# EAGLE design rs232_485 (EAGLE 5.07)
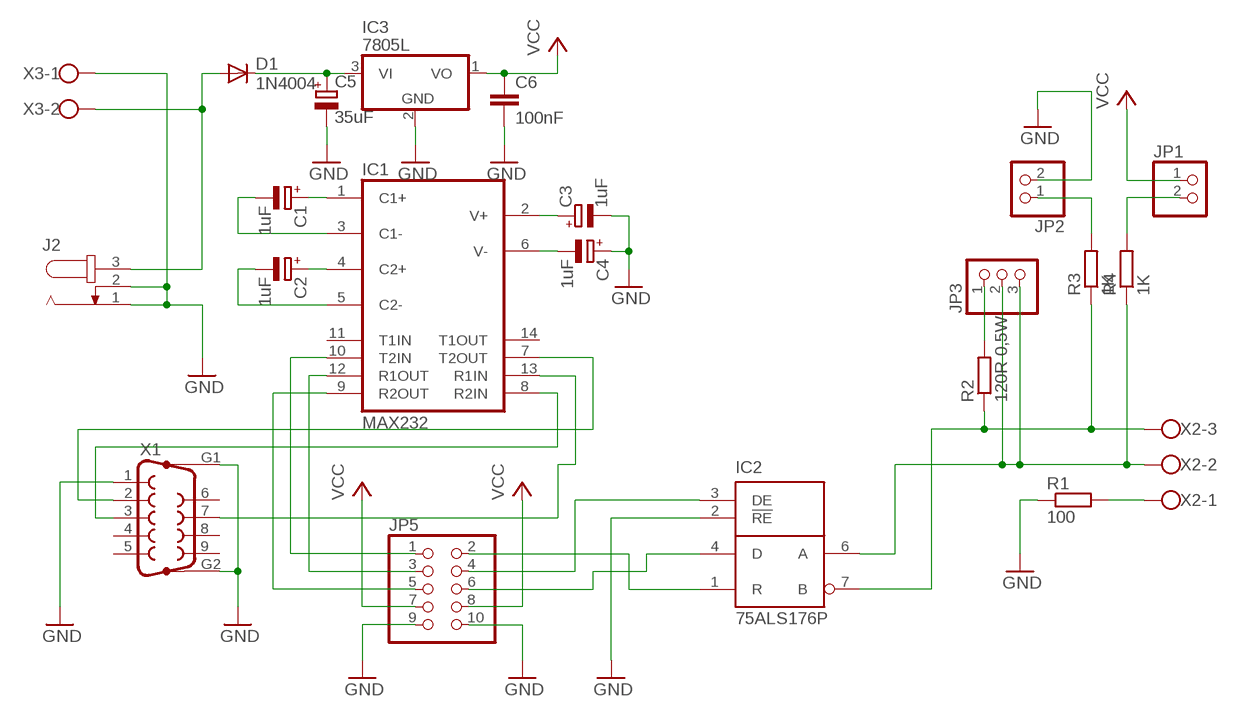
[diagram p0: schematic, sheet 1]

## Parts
C1  1uF  CPOL-EUE2,5-6E  [E2,5-6E]
C2  1uF  CPOL-EUE2,5-6E  [E2,5-6E]
C3  1uF  CPOL-EUE2,5-6E  [E2,5-6E]
C4  1uF  CPOL-EUE2,5-6E  [E2,5-6E]
C5  35uF  CPOL-EUE2.5-5  [E2,5-5]
C6  100nF  C-EU025-025X050  [C025-025X050]
D1  1N4004  [DO41-10]
IC1  MAX232  [DIL16]
IC2  75ALS176P  [DIL08]
IC3  7805L  [TO92]
J2  JACK-PLUG0  [SPC4077]
JP1  PINHD-1X2  [1X02]
JP2  PINHD-1X2  [1X02]
JP3  PINHD-1X3  [1X03]
JP5  PINHD-2X5  [2X05]
R1  100  R-EU_0204/7  [0204/7]
R2  120R 0,5W  R-EU_0204/7  [0204/7]
R3  1K  R-EU_0204/7  [0204/7]
R4  1K  R-EU_0204/7  [0204/7]
X1  F09HP  [F09HP]
X2  W237-103  [W237-103]
X3  W237-102  [W237-102]

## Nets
GND: C3.- C4.+ C5.- C6.2 IC2.2(!RE) IC3.2(GND) J2.1 J2.2 JP2.2 JP5.9 JP5.10 R1.1 X1.1 X1.G1 X1.G2 X3.1
N$1: C1.+ IC1.1(C1+)
N$2: C2.+ IC1.4(C2+)
N$3: C1.- IC1.3(C1-)
N$4: C2.- IC1.5(C2-)
N$5: C3.+ IC1.2(V+)
N$6: C4.- IC1.6(V-)
N$7: IC1.10(T2IN) JP5.1
N$8: IC2.1(R) JP5.2
N$9: IC1.8(R2IN) X1.3
N$10: IC1.7(T2OUT) X1.2
N$11: IC1.13(R1IN) X1.7
N$12: IC1.12(R1OUT) JP5.3
N$13: IC2.4(D) JP5.6
N$14: IC1.9(R2OUT) JP5.5
N$15: IC2.3(DE) JP5.4
N$16: IC2.6(A) JP3.2 JP3.3 R4.1 X2.2
N$17: IC2.7(B) R2.1 R3.1 X2.3
N$18: JP3.1 R2.2
N$19: R1.2 X2.1
N$20: JP1.2 R4.2
N$21: JP2.1 R3.2
N$22: D1.A J2.3 X3.2
N$26: C5.+ D1.C IC3.3(VI)
VCC: C6.1 IC3.1(VO) JP1.1 JP5.7 JP5.8
Unconnected: IC1.11(T1IN) IC1.14(T1OUT) X1.4 X1.5 X1.6 X1.8 X1.9

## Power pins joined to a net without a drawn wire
GND: IC1.15(GND) IC2.5(GND)
VCC: IC1.16(VCC) IC2.8(VCC)

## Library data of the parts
C1-C5 = resistor:CPOL-EU: POLARIZED CAPACITOR, European symbol
C6 = resistor:C-EU: CAPACITOR, European symbol
D1 = diode:1N4004: DIODE
IC1 = maxim:MAX232: RS232 TRANSEIVER
IC2 = texas:75ALS176: DIFFERENTIAL BUS TRANSCEIVERS TIA/EIA-422-B, TIA/EIA-422-B + TIA/EIA-422-B TIA/EIA-422-B Operate at Data Rates up to 35 Mbaud Source: http://focus.ti.com/lit/ds/symlink/sn65als176.pdf
IC3 = linear:78*: Positive VOLTAGE REGULATOR Source: http://cache.national.com/ds/LM/LM78L05.pdf http://www.fairchildsemi.com/ds/LM/LM7805.pdf
J2 = con-jack:JACK-PLUG: DC POWER JACK Power Jack, DC, Right Angle, Through Hole, Rated 5A at 16VDC, PC Terminals Distributor: Farnell (www.Farnell.de) Drawing: 84N1161.pdf / 84N1162.pdf Manufacturer: SPC Technology (www.spctechnology.com) Type: SPC4077 / SPC 4078
JP1 JP2 = pinhead:PINHD-1X2: PIN HEADER
JP3 = pinhead:PINHD-1X3: PIN HEADER
JP5 = pinhead:PINHD-2X5: PIN HEADER
R1-R4 = resistor:R-EU_: RESISTOR, European symbol
X1 = con-subd:F09HP: SUB-D
X2 = con-wago-500:W237-103: WAGO SCREW CLAMP
X3 = con-wago-500:W237-102: WAGO SCREW CLAMP

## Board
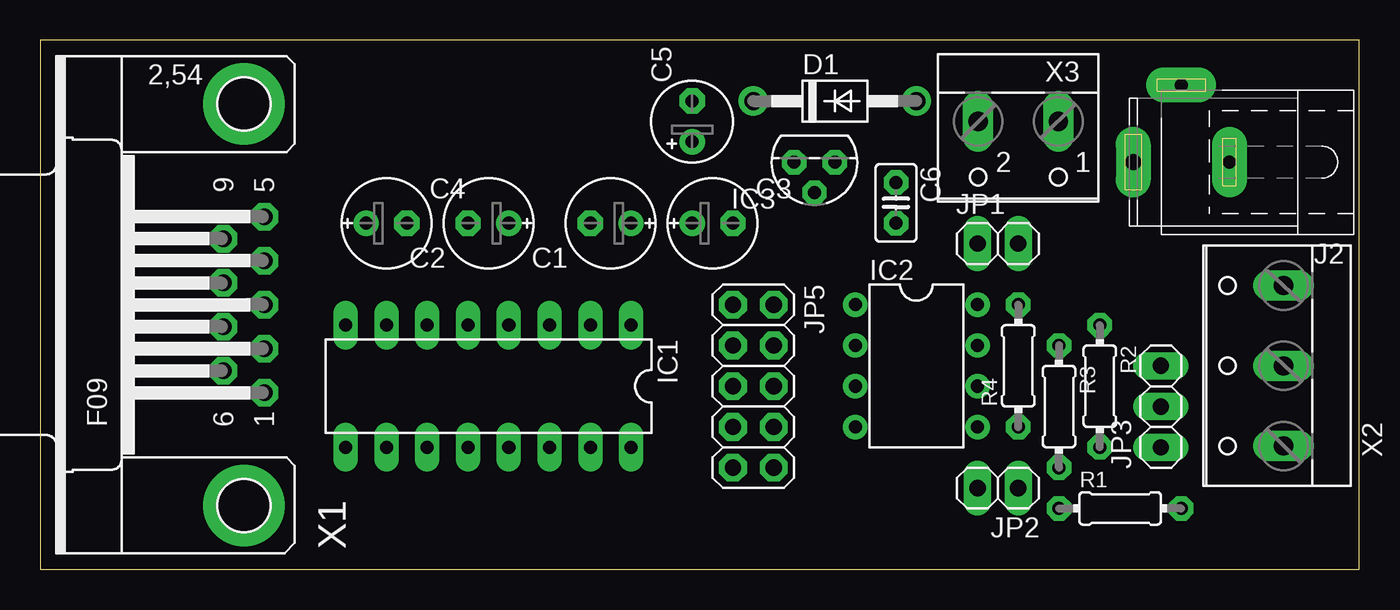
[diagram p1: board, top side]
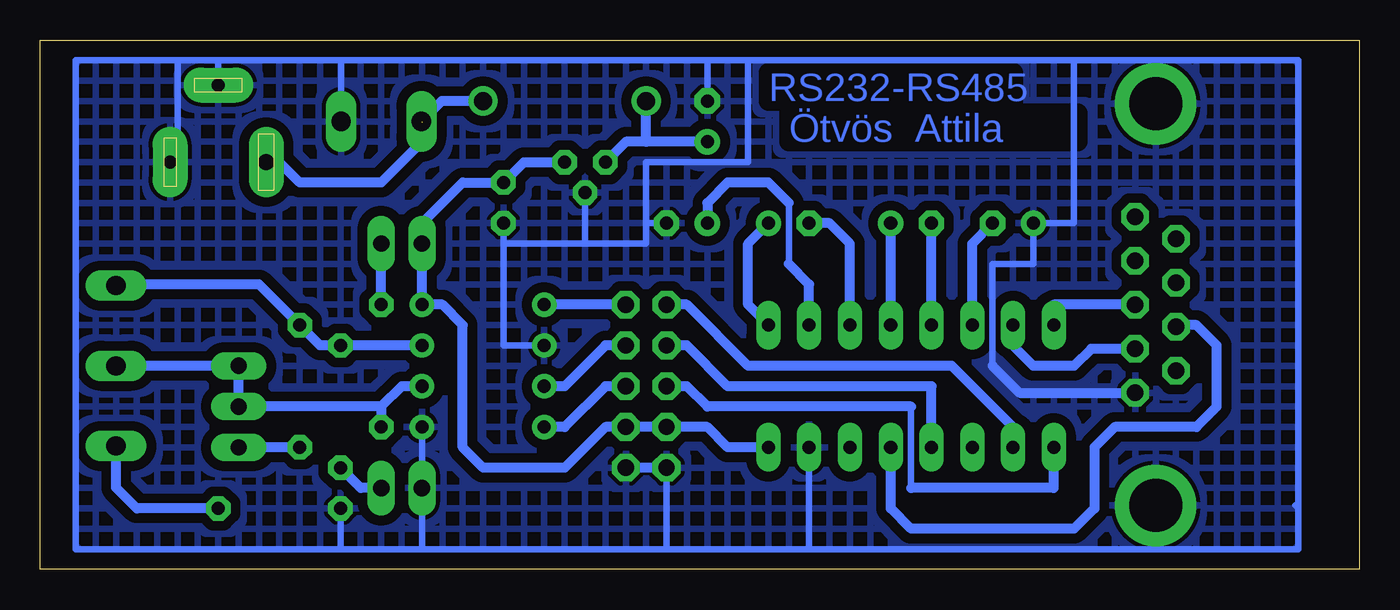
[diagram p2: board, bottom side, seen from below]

Size 82.22 x 33.01 mm. Coordinates in mm from the lower left corner, seen from the top.
Outline: 0,0 82.22,0 82.22,33.01 0,33.01 0,0
Copper layers (1*16): Top 0.035mm / dielectric 1.5mm / Bottom 0.035mm
Design rules "default *": minimum track width 10mil, minimum drill 24mil, track to track 8mil, track to pad 8mil, pad to pad 8mil, via to via 8mil, smd to smd 8mil, copper to edge 40mil, drill to drill 8mil, minimum pad ring 14mil, minimum via ring 12mil, stop-mask expansion 4mil, vias tented up to drill 0mil, thermal gap 10mil

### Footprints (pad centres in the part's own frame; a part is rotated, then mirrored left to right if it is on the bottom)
E2,5-6E = drill 0.813 pad 1.575 round: + -1.27,0 | drill 0.813 pad 1.575 octagon: - 1.27,0
E2,5-5 = drill 0.813 pad 1.6 round: + -1.27,0 | drill 0.813 pad 1.6 octagon: - 1.27,0
C025-025X050 = drill 0.813 octagon: 1 -1.27,0; 2 1.27,0
DO41-10 = drill 1.118 round: A 5.08,0; C -5.08,0
DIL16 = drill 0.813 long: 1 -8.89,-3.81; 2 -6.35,-3.81; 3 -3.81,-3.81; 4 -1.27,-3.81; 5 1.27,-3.81; 6 3.81,-3.81; 7 6.35,-3.81; 8 8.89,-3.81; 9 8.89,3.81; 10 6.35,3.81; 11 3.81,3.81; 12 1.27,3.81; 13 -1.27,3.81; 14 -3.81,3.81; 15 -6.35,3.81; 16 -8.89,3.81
DIL08 = drill 0.813 pad 1.27 round: 1 -3.81,-3.81; 2 -1.27,-3.81; 3 1.27,-3.81; 4 3.81,-3.81; 5 3.81,3.81; 6 1.27,3.81; 7 -1.27,3.81; 8 -3.81,3.81
TO92 = drill 0.813 octagon: 1 -1.27,0; 2 0,1.905; 3 1.27,0
SPC4077 = drill 0.8 pad 2.184 long: 1 -3,0; 2 0,-4.8 | drill 1 pad 2.184 long: 3 3,0
1X02 = drill 1.016 long: 1 -1.27,0; 2 1.27,0
1X03 = drill 1.016 long: 1 -2.54,0; 2 0,0; 3 2.54,0
2X05 = drill 1.016 octagon: 1 -5.08,-1.27; 2 -5.08,1.27; 3 -2.54,-1.27; 4 -2.54,1.27; 5 0,-1.27; 6 0,1.27; 7 2.54,-1.27; 8 2.54,1.27; 9 5.08,-1.27; 10 5.08,1.27
0204/7 = drill 0.813 octagon: 1 -3.81,0; 2 3.81,0
F09HP = drill 1.016 octagon: 1 -5.486,-1.27; 2 -2.743,-1.27; 3 0,-1.27; 4 2.743,-1.27; 5 5.486,-1.27; 6 -4.115,1.27; 7 -1.372,1.27; 8 1.372,1.27; 9 4.115,1.27 | drill 3.302 pad 5.08 round: G1 -12.522,0; G2 12.522,0
W237-103 = drill 1.194 long: 1 -5,-1.29; 2 0,-1.29; 3 5,-1.29
W237-102 = drill 1.194 long: 1 -2.5,-1.27; 2 2.5,-1.27

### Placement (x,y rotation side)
C1  35.56,21.59 180 top
C2  27.94,21.59 180 top
C3  41.91,21.59 0 top
C4  21.59,21.59 0 top
C5  40.64,27.94 90 top
C6  53.34,22.86 270 top
D1  49.53,29.21 0 top
IC1  27.94,11.43 180 top
IC2  54.61,12.7 270 top
IC3  48.26,25.4 180 top
J2  71.12,25.4 180 top
JP1  59.69,20.32 0 top
JP2  59.69,5.08 180 top
JP3  69.85,10.16 90 top
JP5  44.45,11.43 270 top
R1  67.31,3.81 0 top
R2  66.04,11.43 270 top
R3  63.5,10.16 270 top
R4  60.96,12.7 90 top
X1  12.7,16.51 90 top
X2  76.2,12.7 90 top
X3  60.96,26.67 180 top

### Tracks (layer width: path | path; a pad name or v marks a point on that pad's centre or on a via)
GND
  Bottom 0.406: 3.81,3.81 3.99,3.99 | 34.29,1.27 IC1.15 | 53.34,20.32 C6.2 | 44.45,21.59 44.45,20.32 48.26,20.32 | 40.64,31.75 63.5,31.75 | 63.5,31.75 71.12,31.75 | 73.66,31.75 80.01,31.75 80.01,1.27 63.5,1.27 | 73.66,31.75 71.12,31.75 | 71.12,31.75 71.08,31.71 | IC2.2 53.34,13.97 53.34,20.32 | 12.7,31.75 3.81,31.75 3.81,3.81 | 12.7,31.75 17.78,31.75 | 17.78,31.75 38.1,31.75 | 38.1,31.75 40.64,31.75 | 3.81,3.81 3.81,1.27 12.7,1.27 | 12.7,1.27 34.29,1.27 | 34.29,1.27 43.18,1.27 | 43.18,1.27 58.42,1.27 | 58.42,1.27 63.5,1.27 | 58.42,1.27 IC2.5 | 43.18,1.27 JP5.9 | 22.86,12.7 22.86,19.05 20.32,19.05 C4.+ 17.78,21.59 17.78,31.75 | 12.7,1.27 X1.G1 | 12.7,31.75 X1.G2 | 44.45,21.59 C3.- | 48.26,20.32 53.34,20.32 | 40.64,31.75 C5.- | 48.26,20.32 IC3.2 | 63.5,1.27 R1.1 | 38.1,31.75 38.1,25.4 44.45,25.4 44.45,21.59 | X3.1 63.46,31.71 63.5,31.75 | J2.1 73.66,26.67 73.66,31.75 | 71.12,31.75 J2.2
  Bottom 0.61: JP5.9 JP5.10 | X1.1 21.18,11.02 22.86,12.7
  pour Bottom (isolate 0.61, hatched): 3.81,31.75 80.01,31.75 80.01,1.27 3.81,1.27
N$1
  Bottom 0.61: C1.+ 38.1,20.32 38.1,16.51 IC1.1
N$2
  Bottom 0.61: IC1.4 C2.+
N$3
  Bottom 0.61: C1.- 33.02,21.59 31.75,20.32 IC1.3
N$4
  Bottom 0.61: IC1.5 C2.-
N$5
  Bottom 0.406: 35.56,19.05 35.56,22.86
  Bottom 0.61: IC1.2 34.29,17.78 35.56,19.05 | 35.56,22.86 36.83,24.13 39.37,24.13 40.64,22.86 C3.+
N$6
  Bottom 0.61: C4.- 24.13,20.32 IC1.6
N$7
  Bottom 0.61: JP5.1 41.91,16.51 38.1,12.7 25.4,12.7 21.59,8.89 IC1.10
N$8
  Bottom 0.61: JP5.2 IC2.1
N$9
  Bottom 0.61: IC1.8 19.05,16.51 X1.3
N$10
  Bottom 0.61: X1.2 16.71,13.77 17.78,12.7 20.32,12.7 21.59,13.97 IC1.7
N$11
  Bottom 0.61: IC1.13 29.21,3.81 27.94,2.54 17.78,2.54 16.51,3.81 16.51,7.62 15.24,8.89 10.16,8.89 8.89,10.16 8.89,13.97 10.16,15.24 11.33,15.24 X1.7
N$12
  Bottom 0.61: JP5.3 41.91,13.97 39.37,11.43 26.67,11.43 IC1.12
N$13
  Bottom 0.61: JP5.6 46.99,11.43 49.53,8.89 IC2.4
N$14
  Bottom 0.406: 27.94,5.08 27.94,10.16
  Bottom 0.61: JP5.5 41.91,11.43 40.64,10.16 27.94,10.16 | 27.94,5.08 19.05,5.08 IC1.9
N$15
  Bottom 0.61: JP5.4 46.99,13.97 49.53,11.43 IC2.3
N$16
  Bottom 0.61: IC2.6 59.69,11.43 60.96,10.16 | 60.96,10.16 R4.1 | X2.2 JP3.3 JP3.2 60.96,10.16
N$17
  Bottom 0.61: IC2.7 R3.1 64.77,13.97 R2.1 68.58,17.78 77.41,17.78 X2.3
N$18
  Bottom 0.61: R2.2 JP3.1
N$19
  Bottom 0.61: X2.1 77.49,5.1 76.2,3.81 R1.2
N$20
  Bottom 0.61: R4.2 JP1.2
N$21
  Bottom 0.61: R3.2 62.23,5.08 JP2.1
N$22  (1 unrouted)
  Bottom 0.61: J2.3 67.31,25.4 66.04,24.13 60.96,24.13 58.42,26.67 58.42,27.9 | D1.A 57.19,29.21 X3.2
N$26
  Bottom 0.61: C5.+ 44.45,26.67 | 44.45,26.67 D1.C | 44.45,26.67 45.72,26.67 IC3.3
VCC
  Bottom 0.61: IC1.16 39.37,7.62 40.64,8.89 JP5.7 JP5.8 46.99,8.89 49.53,6.35 54.61,6.35 55.88,7.62 55.88,15.24 57.15,16.51 IC2.8 JP1.1 58.42,21.59 55.88,24.13 C6.1 52.07,25.4 IC3.1

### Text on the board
Bottom: RS232-RS485 | Ötvös Attila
